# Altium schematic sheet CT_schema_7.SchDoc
size 251 x 159 mm
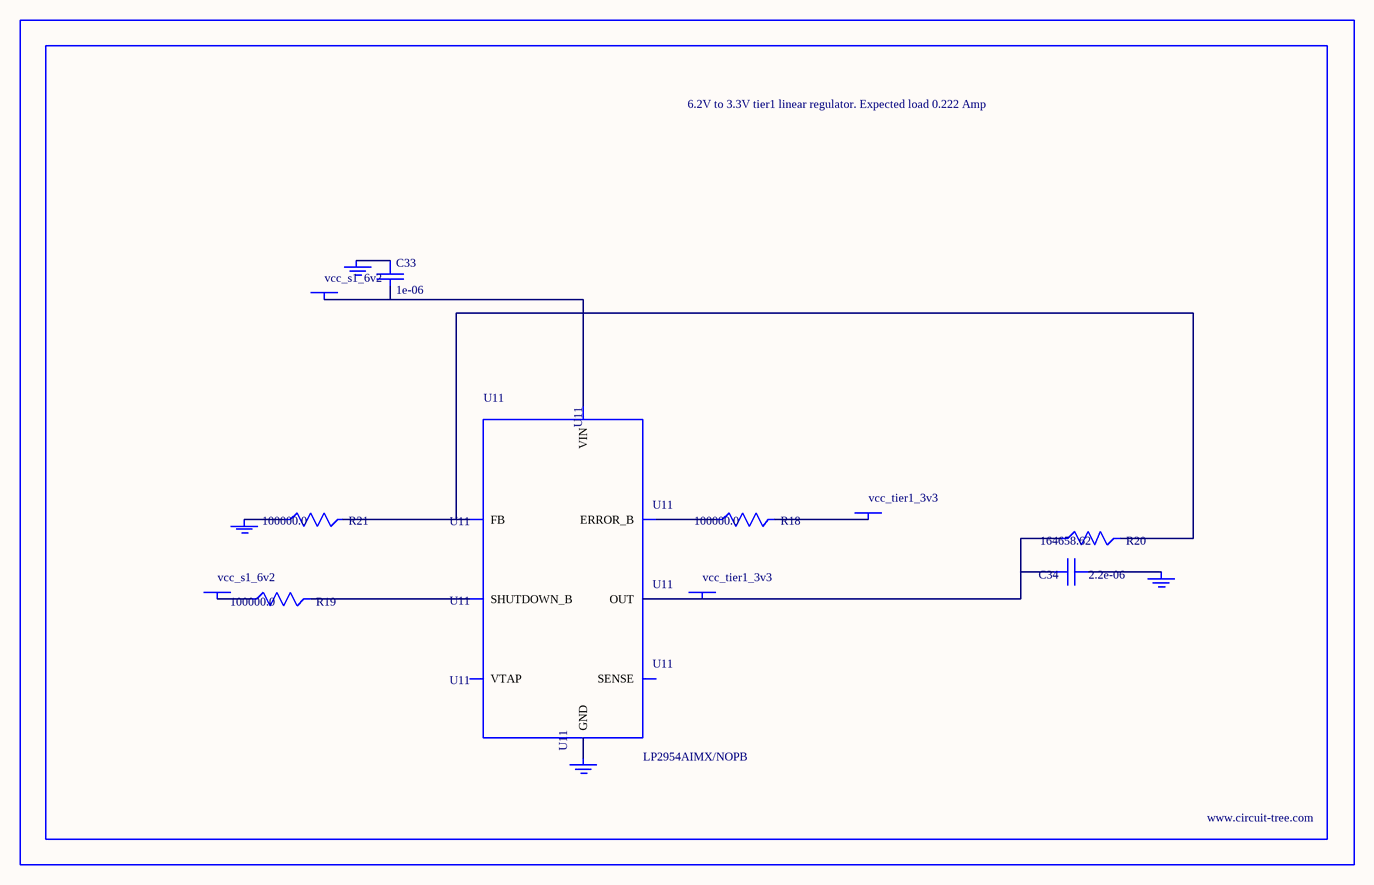
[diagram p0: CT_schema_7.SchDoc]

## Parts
BORDER6  (no value)
C33  1e-06  [EXV-9B]
C34  2.2e-06  [EXV-9B]
GND_INSTANCE_6_0  (no value)
GND_INSTANCE_6_1  (no value)
GND_INSTANCE_6_2  (no value)
GND_INSTANCE_6_3  (no value)
POWER_INSTANCE_6_0  vcc_s1_6v2
POWER_INSTANCE_6_1  vcc_tier1_3v3
POWER_INSTANCE_6_2  vcc_s1_6v2
POWER_INSTANCE_6_3  vcc_tier1_3v3
R18  100000.0  [R0603]
R19  100000.0  [R0603]
R20  164658.62  [R0603]
R21  100000.0  [R0603]
U11  LP2954AIMX/NOPB  [LP2954]

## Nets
NetC33_1: C33.1 GND_INSTANCE_6_2.0(GND)
NetC33_2: C33.2 POWER_INSTANCE_6_2.0(PWR) U11.8(VIN)
NetC34_1: C34.1 GND_INSTANCE_6_0.0(GND)
NetC34_2: C34.2 POWER_INSTANCE_6_3.0(PWR) R20.1 U11.1(OUT)
NetGND_INSTANCE_6_1_0: GND_INSTANCE_6_1.0(GND) R21.1
NetGND_INSTANCE_6_3_0: GND_INSTANCE_6_3.0(GND) U11.4(GND)
NetPOWER_INSTANCE_6_0_0: POWER_INSTANCE_6_0.0(PWR) R19.1
NetPOWER_INSTANCE_6_1_0: POWER_INSTANCE_6_1.0(PWR) R18.2
NetR18_1: R18.1 U11.5(ERROR_B)
NetR19_2: R19.2 U11.3(SHUTDOWN_B)
NetR20_2: R20.2 R21.2 U11.7(FB)

Not connected (* = marked no-connect by the designer): U11 2(SENSE) 6(VTAP)

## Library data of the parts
BORDER6 = BORDER_PAGE6
C33 = EDK105M050A9BAA
C34 = EDK225M050A9BAA
GND_INSTANCE_6_0-GND_INSTANCE_6_3 = GND
POWER_INSTANCE_6_0-POWER_INSTANCE_6_3 = PWR
R18 R19 R21 = RC0603JR-07100KL
R20 = R20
